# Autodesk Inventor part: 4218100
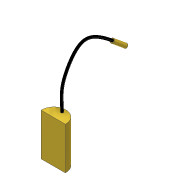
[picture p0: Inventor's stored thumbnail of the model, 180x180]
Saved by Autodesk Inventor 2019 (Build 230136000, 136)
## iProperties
Created: 2020-12
Part Number: 4218100
Material: Generic
Document SubType Name: Modeling
Designer: user
Density: 1 g/cm^3
Appearance: Default
Author: user
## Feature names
1. Extrusion1
2. Extrusion2
3. Sweep1
4. Extrusion3
5. Extrusion4
## Parameters: d6 = 0, d7 = 12 mm, d12 = 466 mm, d15 = 0, d16 = 0, d17 = 0, d18 = 15 mm, d19 = 75 mm, d20 = 0, d21 = 75 mm, d22 = 0
